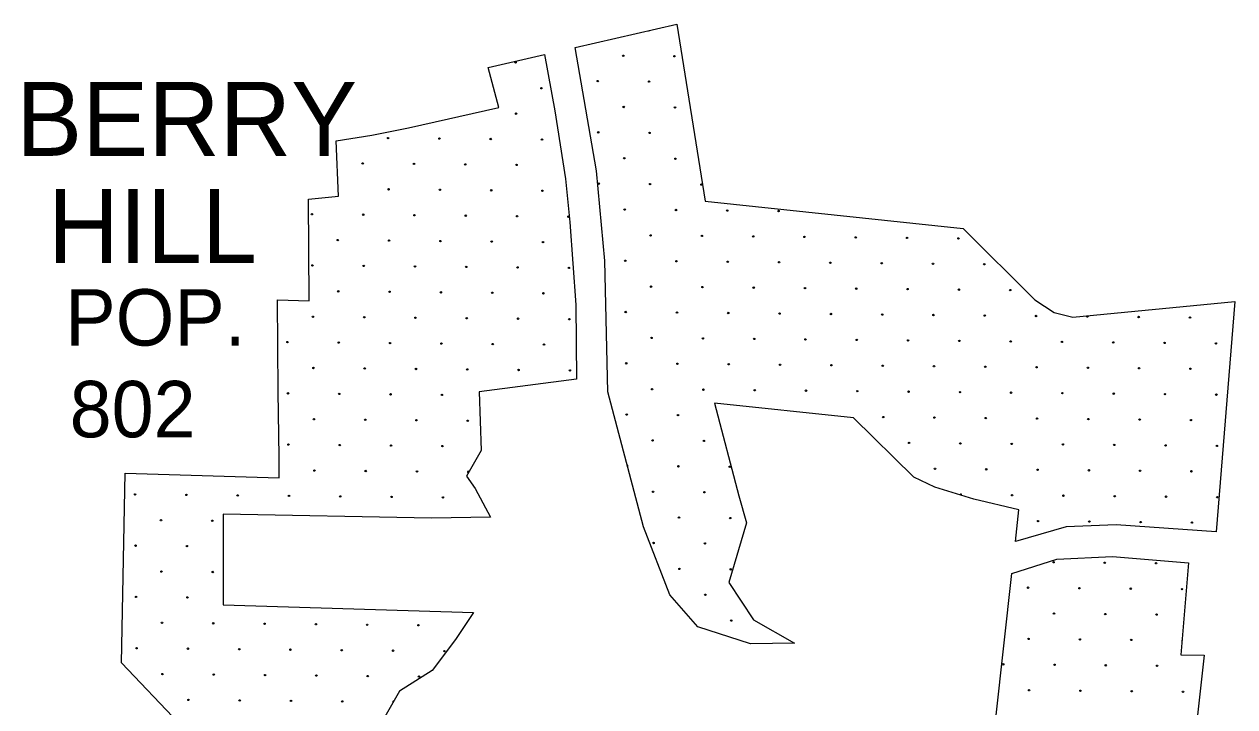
# Model space of a CAD drawing. Extents: x 1612280 to 1883141, y 560852 to 780851.
# Drawn here: x 1735786 to 1744861, y 650639 to 655760 of the extents above; entities that cross this region are included whole.
import ezdxf

# ---------------------------------------------------------------- set-up
doc = ezdxf.new("R2010")
doc.units = 0
for name, color, linetype in [('DESIGN - EROSION CONTROL - Devices', 7, 'Continuous'), ('DESIGN - SCRATCH - User 1', 7, 'Continuous'), ('SURVEY - VEGETATION - Features with Text', 7, 'Continuous')]:
    doc.layers.add(name, color=color, linetype=linetype)

msp = doc.modelspace()

# ---------------------------------------------------------------- linework, layer by layer
at = {"layer": 'DESIGN - EROSION CONTROL - Devices'}
for centre in [(1740276.2, 655523.1), (1740276.2, 655523.1), (1740660.8, 655519.4), (1740660.8, 655519.4), (1739469.5, 655473.1), (1739469.5, 655473.1), (1740085.8, 655332.7), (1740085.8, 655332.7), (1740470.3, 655329), (1740470.3, 655329), (1739663.7, 655279), (1739663.7, 655279), (1740279.9, 655138.6), (1740279.9, 655138.6), (1740664.5, 655134.9), (1740664.5, 655134.9), (1739473.2, 655088.6), (1739473.2, 655088.6), (1740089.5, 654948.2), (1740089.5, 654948.2), (1740474.1, 654944.4), (1740474.1, 654944.4), (1738513.7, 654905.6), (1738513.7, 654905.6), (1738898.3, 654901.9), (1738898.3, 654901.9), (1739282.8, 654898.2), (1739282.8, 654898.2), (1739667.4, 654894.4), (1739667.4, 654894.4), (1738323.3, 654715.2), (1738323.3, 654715.2), (1738707.9, 654711.5), (1738707.9, 654711.5), (1739092.4, 654707.7), (1739092.4, 654707.7), (1739477, 654704), (1739477, 654704), (1740283.7, 654754), (1740283.7, 654754), (1740668.2, 654750.3), (1740668.2, 654750.3), (1738517.5, 654521.1), (1738517.5, 654521.1), (1738902, 654517.3), (1738902, 654517.3), (1739286.6, 654513.6), (1739286.6, 654513.6), (1739671.1, 654509.9), (1739671.1, 654509.9), (1740093.3, 654563.6), (1740093.3, 654563.6), (1740477.8, 654559.9), (1740477.8, 654559.9), (1740862.4, 654556.2), (1740862.4, 654556.2), (1737942.5, 654334.4), (1737942.5, 654334.4), (1738327.1, 654330.7), (1738327.1, 654330.7), (1738711.6, 654326.9), (1738711.6, 654326.9), (1739096.2, 654323.2), (1739096.2, 654323.2), (1739480.7, 654319.5), (1739480.7, 654319.5), (1739865.3, 654315.7), (1739865.3, 654315.7), (1740287.4, 654369.5), (1740287.4, 654369.5), (1740672, 654365.8), (1740672, 654365.8), (1741056.5, 654362), (1741056.5, 654362), (1741441.1, 654358.3), (1741441.1, 654358.3), (1738136.6, 654140.3), (1738136.6, 654140.3), (1738521.2, 654136.5), (1738521.2, 654136.5), (1738905.7, 654132.8), (1738905.7, 654132.8), (1739290.3, 654129), (1739290.3, 654129), (1739674.9, 654125.3), (1739674.9, 654125.3), (1740481.5, 654175.3), (1740481.5, 654175.3), (1740866.1, 654171.6), (1740866.1, 654171.6), (1741250.7, 654167.9), (1741250.7, 654167.9), (1741635.2, 654164.1), (1741635.2, 654164.1), (1742019.8, 654160.4), (1742019.8, 654160.4), (1742404.3, 654156.7), (1742404.3, 654156.7), (1742788.9, 654152.9), (1742788.9, 654152.9), (1737946.2, 653949.8), (1737946.2, 653949.8), (1738330.8, 653946.1), (1738330.8, 653946.1), (1740291.1, 653984.9), (1740291.1, 653984.9), (1740675.7, 653981.2), (1740675.7, 653981.2), (1741060.2, 653977.5), (1741060.2, 653977.5), (1741444.8, 653973.7), (1741444.8, 653973.7), (1741829.3, 653970), (1741829.3, 653970), (1742213.9, 653966.3), (1742213.9, 653966.3), (1742598.5, 653962.5), (1742598.5, 653962.5), (1742983, 653958.8), (1742983, 653958.8), (1738715.3, 653942.4), (1738715.3, 653942.4), (1739099.9, 653938.6), (1739099.9, 653938.6), (1739484.4, 653934.9), (1739484.4, 653934.9), (1739869, 653931.2), (1739869, 653931.2), (1740485.3, 653790.8), (1740485.3, 653790.8), (1740869.8, 653787.1), (1740869.8, 653787.1), (1741254.4, 653783.3), (1741254.4, 653783.3), (1741638.9, 653779.6), (1741638.9, 653779.6), (1742023.5, 653775.9), (1742023.5, 653775.9), (1742408, 653772.1), (1742408, 653772.1), (1742792.6, 653768.4), (1742792.6, 653768.4), (1743177.2, 653764.7), (1743177.2, 653764.7), (1738140.4, 653755.7), (1738140.4, 653755.7), (1738524.9, 653752), (1738524.9, 653752), (1738909.5, 653748.2), (1738909.5, 653748.2), (1739294, 653744.5), (1739294, 653744.5), (1739678.6, 653740.8), (1739678.6, 653740.8), (1740294.9, 653600.4), (1740294.9, 653600.4), (1740679.4, 653596.6), (1740679.4, 653596.6), (1741064, 653592.9), (1741064, 653592.9), (1741448.5, 653589.2), (1741448.5, 653589.2), (1741833.1, 653585.4), (1741833.1, 653585.4), (1742217.6, 653581.7), (1742217.6, 653581.7), (1737950, 653565.3), (1737950, 653565.3), (1738334.5, 653561.6), (1738334.5, 653561.6), (1738719.1, 653557.8), (1738719.1, 653557.8), (1739103.6, 653554.1), (1739103.6, 653554.1), (1739488.2, 653550.4), (1739488.2, 653550.4), (1739872.7, 653546.6), (1739872.7, 653546.6), (1742602.2, 653578), (1742602.2, 653578), (1742986.7, 653574.2), (1742986.7, 653574.2), (1743371.3, 653570.5), (1743371.3, 653570.5), (1743755.8, 653566.8), (1743755.8, 653566.8), (1744140.4, 653563), (1744140.4, 653563), (1744525, 653559.3), (1744525, 653559.3), (1740489, 653406.2), (1740489, 653406.2), (1740873.6, 653402.5), (1740873.6, 653402.5), (1737759.6, 653374.9), (1737759.6, 653374.9), (1738144.1, 653371.1), (1738144.1, 653371.1), (1738528.7, 653367.4), (1738528.7, 653367.4), (1738913.2, 653363.7), (1738913.2, 653363.7), (1739297.8, 653359.9), (1739297.8, 653359.9), (1739682.3, 653356.2), (1739682.3, 653356.2), (1741258.1, 653398.8), (1741258.1, 653398.8), (1741642.7, 653395), (1741642.7, 653395), (1742027.2, 653391.3), (1742027.2, 653391.3), (1742411.8, 653387.6), (1742411.8, 653387.6), (1742796.3, 653383.8), (1742796.3, 653383.8), (1743180.9, 653380.1), (1743180.9, 653380.1), (1743565.4, 653376.4), (1743565.4, 653376.4), (1743950, 653372.6), (1743950, 653372.6), (1744334.5, 653368.9), (1744334.5, 653368.9), (1744719.1, 653365.2), (1744719.1, 653365.2), (1737953.7, 653180.7), (1737953.7, 653180.7), (1738338.3, 653177), (1738338.3, 653177), (1738722.8, 653173.3), (1738722.8, 653173.3), (1739107.4, 653169.5), (1739107.4, 653169.5), (1739491.9, 653165.8), (1739491.9, 653165.8), (1739876.5, 653162.1), (1739876.5, 653162.1), (1740298.6, 653215.8), (1740298.6, 653215.8), (1740683.2, 653212.1), (1740683.2, 653212.1), (1741067.7, 653208.4), (1741067.7, 653208.4), (1741452.3, 653204.6), (1741452.3, 653204.6), (1741836.8, 653200.9), (1741836.8, 653200.9), (1742221.4, 653197.2), (1742221.4, 653197.2), (1742605.9, 653193.4), (1742605.9, 653193.4), (1742990.5, 653189.7), (1742990.5, 653189.7), (1743375, 653186), (1743375, 653186), (1743759.6, 653182.2), (1743759.6, 653182.2), (1744144.1, 653178.5), (1744144.1, 653178.5), (1744528.7, 653174.8), (1744528.7, 653174.8), (1737763.3, 652990.3), (1737763.3, 652990.3), (1738147.8, 652986.6), (1738147.8, 652986.6), (1738532.4, 652982.9), (1738532.4, 652982.9), (1738916.9, 652979.1), (1738916.9, 652979.1), (1740492.7, 653021.7), (1740492.7, 653021.7), (1740877.3, 653018), (1740877.3, 653018), (1741261.9, 653014.2), (1741261.9, 653014.2), (1741646.4, 653010.5), (1741646.4, 653010.5), (1742031, 653006.8), (1742031, 653006.8), (1742415.5, 653003), (1742415.5, 653003), (1742800.1, 652999.3), (1742800.1, 652999.3), (1743184.6, 652995.5), (1743184.6, 652995.5), (1743569.2, 652991.8), (1743569.2, 652991.8), (1743953.7, 652988.1), (1743953.7, 652988.1), (1744338.3, 652984.3), (1744338.3, 652984.3), (1744722.8, 652980.6), (1744722.8, 652980.6), (1737957.4, 652796.2), (1737957.4, 652796.2), (1738342, 652792.4), (1738342, 652792.4), (1738726.5, 652788.7), (1738726.5, 652788.7), (1739111.1, 652785), (1739111.1, 652785), (1740302.3, 652831.3), (1740302.3, 652831.3), (1740686.9, 652827.5), (1740686.9, 652827.5), (1742225.1, 652812.6), (1742225.1, 652812.6), (1742609.7, 652808.9), (1742609.7, 652808.9), (1742994.2, 652805.1), (1742994.2, 652805.1), (1743378.8, 652801.4), (1743378.8, 652801.4), (1743763.3, 652797.7), (1743763.3, 652797.7), (1744147.9, 652793.9), (1744147.9, 652793.9), (1744532.4, 652790.2), (1744532.4, 652790.2), (1737767, 652605.8), (1737767, 652605.8), (1738151.6, 652602), (1738151.6, 652602), (1738536.1, 652598.3), (1738536.1, 652598.3), (1738920.7, 652594.6), (1738920.7, 652594.6), (1740496.5, 652637.1), (1740496.5, 652637.1), (1740881, 652633.4), (1740881, 652633.4), (1742419.2, 652618.5), (1742419.2, 652618.5), (1742803.8, 652614.7), (1742803.8, 652614.7), (1743188.4, 652611), (1743188.4, 652611), (1743572.9, 652607.3), (1743572.9, 652607.3), (1743957.5, 652603.5), (1743957.5, 652603.5), (1744342, 652599.8), (1744342, 652599.8), (1744726.6, 652596.1), (1744726.6, 652596.1), (1737961.2, 652411.6), (1737961.2, 652411.6), (1738345.7, 652407.9), (1738345.7, 652407.9), (1738730.3, 652404.2), (1738730.3, 652404.2), (1740690.6, 652443), (1740690.6, 652443), (1741075.2, 652439.3), (1741075.2, 652439.3), (1742613.4, 652424.3), (1742613.4, 652424.3), (1742997.9, 652420.6), (1742997.9, 652420.6), (1743382.5, 652416.9), (1743382.5, 652416.9), (1743767, 652413.1), (1743767, 652413.1), (1744151.6, 652409.4), (1744151.6, 652409.4), (1744536.2, 652405.7), (1744536.2, 652405.7), (1736617.1, 652232.4), (1736617.1, 652232.4), (1737001.7, 652228.7), (1737001.7, 652228.7), (1737386.2, 652225), (1737386.2, 652225), (1737770.8, 652221.2), (1737770.8, 652221.2), (1740500.2, 652252.6), (1740500.2, 652252.6), (1740884.8, 652248.8), (1740884.8, 652248.8), (1743192.1, 652226.4), (1743192.1, 652226.4), (1743576.6, 652222.7), (1743576.6, 652222.7), (1738155.3, 652217.5), (1738155.3, 652217.5), (1738539.9, 652213.8), (1738539.9, 652213.8), (1738924.4, 652210), (1738924.4, 652210), (1743961.2, 652219), (1743961.2, 652219), (1744345.7, 652215.2), (1744345.7, 652215.2), (1744730.3, 652211.5), (1744730.3, 652211.5), (1736811.2, 652038.3), (1736811.2, 652038.3), (1740694.4, 652058.4), (1740694.4, 652058.4), (1741078.9, 652054.7), (1741078.9, 652054.7), (1737195.8, 652034.5), (1737195.8, 652034.5), (1743386.2, 652032.3), (1743386.2, 652032.3), (1743770.8, 652028.6), (1743770.8, 652028.6), (1744155.3, 652024.8), (1744155.3, 652024.8), (1744539.9, 652021.1), (1744539.9, 652021.1), (1740503.9, 651868), (1740503.9, 651868), (1740888.5, 651864.3), (1740888.5, 651864.3), (1736620.8, 651847.9), (1736620.8, 651847.9), (1737005.4, 651844.1), (1737005.4, 651844.1), (1743502.1, 651723.1), (1743502.1, 651723.1), (1743886.7, 651719.3), (1743886.7, 651719.3), (1744271.2, 651715.6), (1744271.2, 651715.6), (1736815, 651653.7), (1736815, 651653.7), (1737199.5, 651650), (1737199.5, 651650), (1740698.1, 651673.9), (1740698.1, 651673.9), (1741082.6, 651670.1), (1741082.6, 651670.1), (1743311.7, 651532.7), (1743311.7, 651532.7), (1743696.3, 651528.9), (1743696.3, 651528.9), (1744080.8, 651525.2), (1744080.8, 651525.2), (1744465.4, 651521.5), (1744465.4, 651521.5), (1736624.6, 651463.3), (1736624.6, 651463.3), (1737009.1, 651459.6), (1737009.1, 651459.6), (1740892.2, 651479.7), (1740892.2, 651479.7), (1743505.9, 651338.5), (1743505.9, 651338.5), (1743890.4, 651334.8), (1743890.4, 651334.8), (1744275, 651331), (1744275, 651331), (1736818.7, 651269.2), (1736818.7, 651269.2), (1737203.3, 651265.4), (1737203.3, 651265.4), (1737587.8, 651261.7), (1737587.8, 651261.7), (1737972.4, 651258), (1737972.4, 651258), (1738356.9, 651254.2), (1738356.9, 651254.2), (1738741.5, 651250.5), (1738741.5, 651250.5), (1741086.4, 651285.6), (1741086.4, 651285.6), (1743315.5, 651148.1), (1743315.5, 651148.1), (1743700, 651144.4), (1743700, 651144.4), (1744084.6, 651140.6), (1744084.6, 651140.6), (1736628.3, 651078.8), (1736628.3, 651078.8), (1737012.9, 651075), (1737012.9, 651075), (1737397.4, 651071.3), (1737397.4, 651071.3), (1737782, 651067.6), (1737782, 651067.6), (1738166.5, 651063.8), (1738166.5, 651063.8), (1738551.1, 651060.1), (1738551.1, 651060.1), (1738935.6, 651056.4), (1738935.6, 651056.4), (1743125, 650957.7), (1743125, 650957.7), (1743509.6, 650954), (1743509.6, 650954), (1743894.2, 650950.2), (1743894.2, 650950.2), (1736822.4, 650884.6), (1736822.4, 650884.6), (1737207, 650880.9), (1737207, 650880.9), (1737591.5, 650877.2), (1737591.5, 650877.2), (1737976.1, 650873.4), (1737976.1, 650873.4), (1738360.7, 650869.7), (1738360.7, 650869.7), (1738745.2, 650866), (1738745.2, 650866), (1744278.7, 650946.5), (1744278.7, 650946.5), (1737016.6, 650690.5), (1737016.6, 650690.5), (1737401.1, 650686.7), (1737401.1, 650686.7), (1737785.7, 650683), (1737785.7, 650683), (1738170.2, 650679.3), (1738170.2, 650679.3), (1743319.2, 650763.5), (1743319.2, 650763.5), (1743703.7, 650759.8), (1743703.7, 650759.8), (1744088.3, 650756.1), (1744088.3, 650756.1), (1744472.9, 650752.3), (1744472.9, 650752.3)]:
    msp.add_circle(centre, 5.28, dxfattribs=at)
for centre, start, end in [((1740466.6, 655713.6), 217.17214, 348.51602), ((1740306.1, 652446.7), 304.35623, 85.07495), ((1739114.8, 652400.4), 5.19194, 294.97454), ((1742807.5, 652230.2), 305.79227, 200.36688), ((1744469.1, 651136.9), 143.49516, 206.7815), ((1738554.8, 650675.5), 69.83002, 230.3362)]:
    msp.add_arc(centre, 5.28, start, end, dxfattribs=at)
at = {"layer": 'DESIGN - SCRATCH - User 1'}
for points in [[(1739917.1, 655586), (1740678.6, 655759.7)], [(1739917.1, 655586), (1740678.6, 655759.7)], [(1740678.6, 655759.7), (1740890.7, 654431.6)], [(1740678.6, 655759.7), (1740890.7, 654431.6)], [(1741561, 651117.4), (1741229.8, 651111.6), (1740834.7, 651239.5), (1740625.5, 651477.9), (1740428, 651989.6), (1740162.2, 653001.4), (1740137.4, 653983.9), (1740075, 654659.8), (1739917.1, 655586)], [(1741561, 651117.4), (1741229.8, 651111.6), (1740834.7, 651239.5), (1740625.5, 651477.9), (1740428, 651989.6), (1740162.2, 653001.4), (1740137.4, 653983.9), (1740075, 654659.8), (1739917.1, 655586)], [(1738391.6, 654927.1), (1738667.4, 654981), (1739344.3, 655135.1), (1739262.9, 655434.5), (1739686.6, 655533.5)], [(1738391.6, 654927.1), (1738667.4, 654981), (1739344.3, 655135.1), (1739262.9, 655434.5), (1739686.6, 655533.5)], [(1739686.6, 655533.5), (1739762.7, 655108.9), (1739844, 654600.2), (1739876, 654274.6), (1739922.4, 653655.4), (1739926.8, 653095.7), (1739197.6, 653002.7)], [(1739686.6, 655533.5), (1739762.7, 655108.9), (1739844, 654600.2), (1739876, 654274.6), (1739922.4, 653655.4), (1739926.8, 653095.7), (1739197.6, 653002.7)], [(1736542.7, 652390.9), (1737696.2, 652357.4), (1737696.2, 652514.3), (1737690.4, 653002.7), (1737685.9, 653691.2), (1737923.1, 653685.1), (1737917.1, 654446.1), (1738142.1, 654470.5), (1738123.9, 654884.5), (1738391.6, 654927.1)], [(1736542.7, 652390.9), (1737696.2, 652357.4), (1737696.2, 652514.3), (1737690.4, 653002.7), (1737685.9, 653691.2), (1737923.1, 653685.1), (1737917.1, 654446.1), (1738142.1, 654470.5), (1738123.9, 654884.5), (1738391.6, 654927.1)], [(1740890.7, 654431.6), (1742824.9, 654227.9)], [(1740890.7, 654431.6), (1742824.9, 654227.9)], [(1742824.9, 654227.9), (1743361.5, 653690.9), (1743506.9, 653595.7), (1743647, 653562.2), (1744861, 653680.3)], [(1742824.9, 654227.9), (1743361.5, 653690.9), (1743506.9, 653595.7), (1743647, 653562.2), (1744861, 653680.3)], [(1744861, 653680.3), (1744720.6, 651951.5)], [(1744861, 653680.3), (1744720.6, 651951.5)], [(1739197.6, 653002.7), (1739212.1, 652560.8), (1739101.7, 652368.9), (1739165.6, 652275.9), (1739281.8, 652060.8), (1738840.2, 652055), (1737277.2, 652084), (1737277.2, 651403.8), (1739154, 651345.6)], [(1739197.6, 653002.7), (1739212.1, 652560.8), (1739101.7, 652368.9), (1739165.6, 652275.9), (1739281.8, 652060.8), (1738840.2, 652055), (1737277.2, 652084), (1737277.2, 651403.8), (1739154, 651345.6)], [(1743243.2, 652116.4), (1742903.9, 652197.5), (1742612.7, 652286.1), (1742455.9, 652361.7), (1742003.8, 652806.1), (1740960.1, 652916)], [(1740960.1, 652916), (1741142.7, 652220.6), (1741200.8, 652018.6), (1741067.1, 651570.9), (1741253.1, 651291.9), (1741561, 651117.4)], [(1743243.2, 652116.4), (1742903.9, 652197.5), (1742612.7, 652286.1), (1742455.9, 652361.7), (1742003.8, 652806.1), (1740960.1, 652916)], [(1740960.1, 652916), (1741142.7, 652220.6), (1741200.8, 652018.6), (1741067.1, 651570.9), (1741253.1, 651291.9), (1741561, 651117.4)], [(1737379.6, 650057.8), (1736516.4, 650970), (1736542.7, 652390.9)], [(1737379.6, 650057.8), (1736516.4, 650970), (1736542.7, 652390.9)], [(1743217, 651880.1), (1743243.2, 652116.4)], [(1743217, 651880.1), (1743243.2, 652116.4)], [(1744720.6, 651951.5), (1743972.4, 652004.1), (1743597.6, 651989.6), (1743217, 651880.1)], [(1744720.6, 651951.5), (1743972.4, 652004.1), (1743597.6, 651989.6), (1743217, 651880.1)], [(1743190.2, 651638.8), (1743527.9, 651745.4), (1743943.4, 651765.7), (1744514.2, 651719.8)], [(1743190.2, 651638.8), (1743527.9, 651745.4), (1743943.4, 651765.7), (1744514.2, 651719.8)], [(1744514.2, 651719.8), (1744455.3, 651027.7), (1744631.2, 651025.4)], [(1744514.2, 651719.8), (1744455.3, 651027.7), (1744631.2, 651025.4)], [(1742949.1, 649468), (1743190.2, 651638.8)], [(1742949.1, 649468), (1743190.2, 651638.8)], [(1739154, 651345.6), (1739018.1, 651145.1), (1738843.8, 650912.5), (1738599.8, 650755.5), (1738489.4, 650563.7), (1738355.7, 650482.2), (1738506.8, 650313.6), (1737960.6, 650156.6), (1737379.6, 650057.8)], [(1739154, 651345.6), (1739018.1, 651145.1), (1738843.8, 650912.5), (1738599.8, 650755.5), (1738489.4, 650563.7), (1738355.7, 650482.2), (1738506.8, 650313.6), (1737960.6, 650156.6), (1737379.6, 650057.8)], [(1744631.2, 651025.4), (1744339, 648393.7), (1743535.2, 648490.8), (1741710.6, 648659.4), (1741193.5, 648612.9), (1741123.8, 648694.3), (1740955.3, 648665.2), (1740965, 649036.2)], [(1744631.2, 651025.4), (1744339, 648393.7), (1743535.2, 648490.8), (1741710.6, 648659.4), (1741193.5, 648612.9), (1741123.8, 648694.3), (1740955.3, 648665.2), (1740965, 649036.2)]]:
    msp.add_lwpolyline(points, dxfattribs=at)

# ---------------------------------------------------------------- texts
at = {"layer": 'SURVEY - VEGETATION - Features with Text'}
for s, height, p in [('BERRY', 554.99, (1735725.1, 654771.9)), ('BERRY', 554.99, (1735725.1, 654771.9)), ('HILL', 554.99, (1735962.3, 653969.1)), ('HILL', 554.99, (1735962.3, 653969.1)), ('POP.', 422.99, (1736094, 653348.8)), ('POP.', 422.99, (1736094, 653348.8)), ('802', 422.99, (1736126.7, 652660.7)), ('802', 422.99, (1736126.7, 652660.7))]:
    msp.add_text(s, height=height, rotation=0.00002, dxfattribs=at).set_placement(p)

doc.saveas('drawing.dxf')
